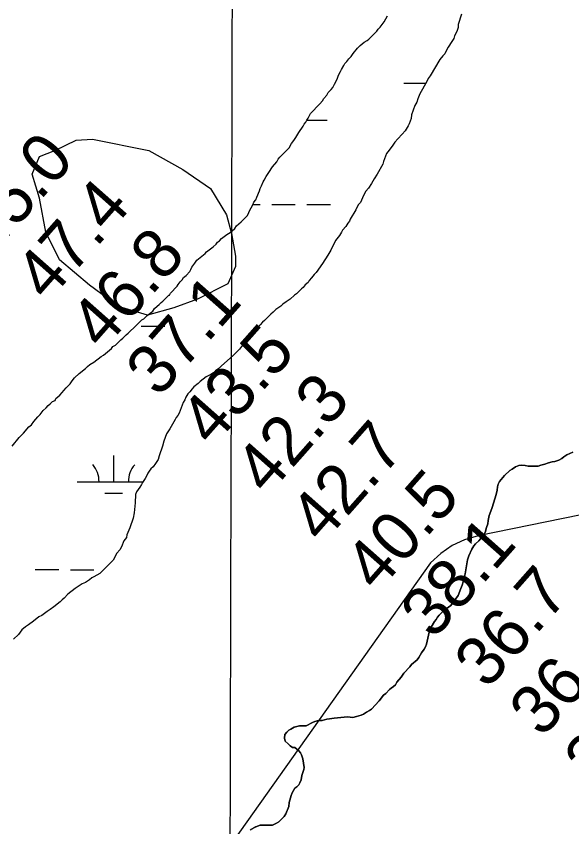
# Model space of a CAD drawing. Extents: x 3172297 to 3210190, y 958463 to 983887.
# Drawn here: x 3191893 to 3192652, y 964695 to 965801 of the extents above; entities that cross this region are included whole.
import ezdxf

# ---------------------------------------------------------------- set-up
doc = ezdxf.new("R2010")
doc.units = 0
for name, color, linetype in [('V-GRID-MAJR', 7, 'Continuous'), ('V-RIVR-RANG', 7, 'Continuous'), ('V-SITE-VEGE', 7, 'Continuous'), ('V-TOPO-MAJR', 7, 'Continuous'), ('V-TOPO-MINR', 7, 'Continuous'), ('V-TOPO-SHOR', 7, 'Continuous'), ('V-WETL-SWMP', 7, 'Continuous')]:
    doc.layers.add(name, color=color, linetype=linetype)

msp = doc.modelspace()

# ---------------------------------------------------------------- linework, layer by layer
at = {"layer": 'V-GRID-MAJR'}
msp.add_spline([(3192183.6, 963880.8), (3192198.6, 969940.7), (3192213.6, 976004.1), (3192228.6, 982067.5), (3192228.6, 982070.9)], degree=3, dxfattribs=at)
at = {"layer": 'V-SITE-VEGE'}
for p, q in [((3192641.5, 965200.1), (3192645.6, 965202.9)), ((3192645.6, 965202.9), (3192649.4, 965204.6)), ((3192649.4, 965204.6), (3192653.8, 965206.4)), ((3192615.3, 965190), (3192620.5, 965191.8)), ((3192620.5, 965191.8), (3192625.3, 965193.2)), ((3192625.3, 965193.2), (3192629.1, 965193.9)), ((3192629.1, 965193.9), (3192634.6, 965195.6)), ((3192634.6, 965195.6), (3192638.7, 965198)), ((3192638.7, 965198), (3192641.5, 965200.1)), ((3192560.3, 965174.4), (3192567.8, 965181.3)), ((3192567.8, 965181.3), (3192570.6, 965183.4)), ((3192570.6, 965183.4), (3192575.4, 965186.5)), ((3192575.4, 965186.5), (3192579.8, 965188.2)), ((3192579.8, 965188.2), (3192582.9, 965188.6)), ((3192582.9, 965188.6), (3192588.8, 965188.2)), ((3192588.8, 965188.2), (3192592.9, 965187.2)), ((3192592.9, 965187.2), (3192606.4, 965187.3)), ((3192606.4, 965187.3), (3192610.1, 965188.7)), ((3192610.1, 965188.7), (3192615.3, 965190)), ((3192553.7, 965166.4), (3192555.8, 965169.2)), ((3192555.8, 965169.2), (3192560.3, 965174.4)), ((3192550.3, 965154.4), (3192550.7, 965159.2)), ((3192550.7, 965159.2), (3192551.7, 965162.6)), ((3192551.7, 965162.6), (3192553.7, 965166.4)), ((3192543.5, 965130.9), (3192549, 965148.8)), ((3192549, 965148.8), (3192550.3, 965154.4)), ((3192539.4, 965119.9), (3192541.5, 965126.1)), ((3192541.5, 965126.1), (3192543.5, 965130.9)), ((3192538.1, 965113), (3192539.4, 965119.9)), ((3192534, 965096.8), (3192535.7, 965103.7)), ((3192535.7, 965103.7), (3192537.4, 965108.5)), ((3192537.4, 965108.5), (3192538.1, 965113)), ((3192525.1, 965085.4), (3192532.3, 965093.7)), ((3192532.3, 965093.7), (3192534, 965096.8)), ((3192518.5, 965078.8), (3192520.6, 965081.2)), ((3192520.6, 965081.2), (3192525.1, 965085.4)), ((3192511.7, 965065), (3192515.5, 965074.3)), ((3192515.5, 965074.3), (3192518.5, 965078.8)), ((3192506.6, 965040.2), (3192510, 965059.5)), ((3192510, 965059.5), (3192511.7, 965065)), ((3192503.9, 965029.5), (3192506.6, 965040.2)), ((3192500.8, 965020.2), (3192502.5, 965025)), ((3192502.5, 965025), (3192503.9, 965029.5)), ((3192497.1, 965010.9), (3192500.8, 965020.2)), ((3192486.8, 964997.4), (3192497.1, 965010.9)), ((3192478.9, 964991.2), (3192486.8, 964997.4)), ((3192466.9, 964978.1), (3192468.6, 964981.2)), ((3192468.6, 964981.2), (3192471, 964983.9)), ((3192471, 964983.9), (3192474.7, 964987.7)), ((3192474.7, 964987.7), (3192478.9, 964991.2)), ((3192460.3, 964967.7), (3192464.8, 964975.3)), ((3192464.8, 964975.3), (3192466.9, 964978.1)), ((3192453.9, 964944.3), (3192457.3, 964960.8)), ((3192457.3, 964960.8), (3192458.6, 964963.6)), ((3192458.6, 964963.6), (3192460.3, 964967.7)), ((3192447, 964932.5), (3192450.8, 964937.4)), ((3192450.8, 964937.4), (3192452.2, 964940.8)), ((3192452.2, 964940.8), (3192453.9, 964944.3)), ((3192440.9, 964922.9), (3192443.3, 964926.3)), ((3192443.3, 964926.3), (3192447, 964932.5)), ((3192430.9, 964913.5), (3192433.3, 964916.7)), ((3192433.3, 964916.7), (3192440.9, 964922.9)), ((3192419.2, 964899.4), (3192423, 964904.9)), ((3192423, 964904.9), (3192430.9, 964913.5)), ((3192411.3, 964889), (3192413.4, 964892.5)), ((3192413.4, 964892.5), (3192419.2, 964899.4)), ((3192398.3, 964877.3), (3192403.4, 964882.5)), ((3192403.4, 964882.5), (3192405.5, 964884.2)), ((3192405.5, 964884.2), (3192408.9, 964886.6)), ((3192408.9, 964886.6), (3192411.3, 964889)), ((3192389, 964867.3), (3192395.2, 964874.9)), ((3192395.2, 964874.9), (3192398.3, 964877.3)), ((3192378.7, 964855.5), (3192389, 964867.3)), ((3192364.3, 964847.5), (3192367.7, 964848.9)), ((3192367.7, 964848.9), (3192371.9, 964851.7)), ((3192371.9, 964851.7), (3192376, 964853.8)), ((3192376, 964853.8), (3192378.7, 964855.5)), ((3192289.2, 964832.8), (3192297.8, 964837.7)), ((3192297.8, 964837.7), (3192301.3, 964839.1)), ((3192301.3, 964839.1), (3192306.1, 964840.1)), ((3192306.1, 964840.1), (3192311.3, 964840.1)), ((3192311.3, 964840.1), (3192317.8, 964841.9)), ((3192317.8, 964841.9), (3192321.3, 964842.6)), ((3192321.3, 964842.6), (3192327.8, 964843.3)), ((3192327.8, 964843.3), (3192332.3, 964844)), ((3192332.3, 964844), (3192346, 964845.1)), ((3192346, 964845.1), (3192353.3, 964844.4)), ((3192353.3, 964844.4), (3192358.1, 964845.5)), ((3192358.1, 964845.5), (3192364.3, 964847.5)), ((3192263.1, 964824.5), (3192265.5, 964826.9)), ((3192265.5, 964826.9), (3192268.3, 964828.6)), ((3192268.3, 964828.6), (3192273.1, 964831.1)), ((3192273.1, 964831.1), (3192280.3, 964832.8)), ((3192280.3, 964832.8), (3192289.2, 964832.8)), ((3192259.7, 964816.2), (3192260, 964821)), ((3192260.7, 964812.1), (3192259.7, 964816.2)), ((3192260, 964821), (3192263.1, 964824.5)), ((3192264.9, 964808.3), (3192260.7, 964812.1)), ((3192267.3, 964805.6), (3192264.9, 964808.3)), ((3192270.7, 964803.2), (3192267.3, 964805.6)), ((3192273.8, 964803.5), (3192270.7, 964803.2)), ((3192279.4, 964799), (3192273.8, 964803.5)), ((3192281.4, 964796.3), (3192279.4, 964799)), ((3192283.2, 964793.2), (3192281.4, 964796.3)), ((3192284.9, 964788), (3192283.2, 964793.2)), ((3192286.7, 964776.3), (3192284.9, 964788)), ((3192283.6, 964765), (3192286.3, 964773.2)), ((3192286.3, 964773.2), (3192286.7, 964776.3)), ((3192280.9, 964755.3), (3192282.6, 964759.4)), ((3192282.6, 964759.4), (3192283.6, 964765)), ((3192274, 964747.7), (3192276.4, 964749.8)), ((3192276.4, 964749.8), (3192279.2, 964752.5)), ((3192279.2, 964752.5), (3192280.9, 964755.3)), ((3192266.2, 964728.4), (3192268.9, 964737.7)), ((3192268.9, 964737.7), (3192270.3, 964741.5)), ((3192270.3, 964741.5), (3192272, 964744.9)), ((3192272, 964744.9), (3192274, 964747.7)), ((3192265.5, 964722.9), (3192266.2, 964728.4)), ((3192261.7, 964712.9), (3192265.5, 964722.9)), ((3192251.8, 964701.8), (3192259.3, 964709.4)), ((3192259.3, 964709.4), (3192261.7, 964712.9)), ((3192220.8, 964695.2), (3192226.7, 964697.3)), ((3192226.7, 964697.3), (3192230.1, 964697.6)), ((3192230.1, 964697.6), (3192234.6, 964697.3)), ((3192234.6, 964697.3), (3192243.2, 964697.3)), ((3192243.2, 964697.3), (3192249, 964700.1)), ((3192249, 964700.1), (3192251.8, 964701.8))]:
    msp.add_line(p, q, dxfattribs=at)
at = {"layer": 'V-TOPO-MAJR'}
msp.add_lwpolyline([(3192687.3, 965125.5), (3192524.2, 965092.4), (3192505.9, 965086.8), (3192488.7, 965079.1), (3192473.4, 965068.3), (3192459.1, 965055.5), (3191992.7, 964398.3), (3191849.4, 964157.8)], dxfattribs=at)
at = {"layer": 'V-TOPO-MINR'}
msp.add_lwpolyline([(3192182.3, 965436), (3192141.1, 965415.5), (3192108.4, 965403.5), (3192072.4, 965393.3), (3192032.9, 965405.4), (3191993.5, 965434.6), (3191952.4, 965469), (3191933.6, 965506.8), (3191925.1, 965553.2), (3191914.8, 965585.8), (3191925.2, 965609.8), (3191945.8, 965618.4), (3191975, 965632.1), (3191997.3, 965633.7), (3192074.5, 965618.2), (3192120.8, 965592.3), (3192158.5, 965566.5), (3192180.7, 965530.4), (3192187.5, 965504.7), (3192192.6, 965473.8), (3192192.6, 965460)], close=True, dxfattribs=at)
at = {"layer": 'V-TOPO-SHOR'}
for points in [[(3192653.8, 965206.4), (3192649.4, 965204.6), (3192645.6, 965202.9), (3192641.5, 965200.1), (3192638.7, 965198), (3192634.6, 965195.6), (3192629.1, 965193.9), (3192625.3, 965193.2), (3192620.5, 965191.8), (3192615.3, 965190), (3192610.1, 965188.7), (3192606.4, 965187.3), (3192592.9, 965187.2), (3192588.8, 965188.2), (3192582.9, 965188.6), (3192579.8, 965188.2), (3192575.4, 965186.5), (3192570.6, 965183.4), (3192567.8, 965181.3), (3192560.3, 965174.4), (3192555.8, 965169.2), (3192553.7, 965166.4), (3192551.7, 965162.6), (3192550.7, 965159.2), (3192550.3, 965154.4), (3192549, 965148.8), (3192543.5, 965130.9)], [(3192543.5, 965130.9), (3192541.5, 965126.1), (3192539.4, 965119.9), (3192538.1, 965113), (3192537.4, 965108.5), (3192535.7, 965103.7), (3192534, 965096.8), (3192532.3, 965093.7), (3192525.1, 965085.4), (3192520.6, 965081.2), (3192518.5, 965078.8), (3192515.5, 965074.3), (3192511.7, 965065), (3192510, 965059.5), (3192506.6, 965040.2), (3192503.9, 965029.5), (3192502.5, 965025), (3192500.8, 965020.2), (3192497.1, 965010.9), (3192486.8, 964997.4), (3192478.9, 964991.2), (3192474.7, 964987.7), (3192471, 964983.9), (3192468.6, 964981.2), (3192466.9, 964978.1), (3192464.8, 964975.3), (3192460.3, 964967.7), (3192458.6, 964963.6), (3192457.3, 964960.8), (3192453.9, 964944.3), (3192452.2, 964940.8), (3192450.8, 964937.4), (3192447, 964932.5), (3192443.3, 964926.3), (3192440.9, 964922.9), (3192433.3, 964916.7), (3192430.9, 964913.5), (3192423, 964904.9), (3192419.2, 964899.4), (3192413.4, 964892.5), (3192411.3, 964889), (3192408.9, 964886.6), (3192405.5, 964884.2), (3192403.4, 964882.5), (3192398.3, 964877.3), (3192395.2, 964874.9), (3192389, 964867.3), (3192378.7, 964855.5), (3192376, 964853.8), (3192371.9, 964851.7), (3192367.7, 964848.9), (3192364.3, 964847.5), (3192358.1, 964845.5), (3192353.3, 964844.4), (3192346, 964845.1), (3192332.3, 964844), (3192327.8, 964843.3), (3192321.3, 964842.6), (3192317.8, 964841.9), (3192311.3, 964840.1), (3192306.1, 964840.1), (3192301.3, 964839.1), (3192297.8, 964837.7), (3192289.2, 964832.8), (3192280.3, 964832.8), (3192273.1, 964831.1), (3192268.3, 964828.6), (3192265.5, 964826.9), (3192263.1, 964824.5), (3192260, 964821), (3192259.7, 964816.2), (3192260.7, 964812.1), (3192264.9, 964808.3), (3192267.3, 964805.6), (3192270.7, 964803.2), (3192273.8, 964803.5), (3192279.4, 964799), (3192281.4, 964796.3), (3192283.2, 964793.2), (3192284.9, 964788), (3192286.7, 964776.3), (3192286.3, 964773.2), (3192283.6, 964765), (3192282.6, 964759.4), (3192280.9, 964755.3), (3192279.2, 964752.5), (3192276.4, 964749.8), (3192274, 964747.7), (3192272, 964744.9), (3192270.3, 964741.5), (3192268.9, 964737.7), (3192266.2, 964728.4), (3192265.5, 964722.9), (3192261.7, 964712.9), (3192259.3, 964709.4), (3192251.8, 964701.8), (3192249, 964700.1), (3192243.2, 964697.3), (3192234.6, 964697.3), (3192230.1, 964697.6), (3192226.7, 964697.3)], [(3192226.7, 964697.3), (3192220.8, 964695.2), (3192212.9, 964690.7)]]:
    msp.add_lwpolyline(points, dxfattribs=at)
at = {"layer": 'V-WETL-SWMP'}
for p, q in [((3192422.8, 965710.3), (3192452.8, 965710.2)), ((3192290.3, 965659.8), (3192318.1, 965659.8)), ((3192216.6, 965544.6), (3192226.4, 965544.6)), ((3192242.4, 965544.5), (3192274.4, 965544.4)), ((3192290.4, 965544.4), (3192322.4, 965544.3)), ((3192064.1, 965378.5), (3192096.1, 965378.4)), ((3192026.4, 965166), (3192026.5, 965202)), ((3191976.4, 965166.1), (3192066.3, 965165.9)), ((3192014.4, 965150.6), (3192038.4, 965150.5)), ((3191919.3, 965046.1), (3191951.3, 965046.1)), ((3191967.3, 965046), (3191999.3, 965046))]:
    msp.add_line(p, q, dxfattribs=at)
for points in [[(3192501.5, 965804.1), (3192496.9, 965790), (3192496.9, 965786), (3192495.6, 965781.9), (3192494.2, 965778.6), (3192492.2, 965774.5), (3192490.9, 965771.1), (3192488.2, 965767.1), (3192483.5, 965759), (3192480.8, 965754.3), (3192478.8, 965750.3), (3192476.2, 965747.6), (3192472.1, 965742.2), (3192458.8, 965719.9), (3192456.1, 965716.5), (3192454.1, 965712.5), (3192444.7, 965695.6), (3192442, 965688.9), (3192440.7, 965684.2), (3192438, 965679.5), (3192433.4, 965666.7), (3192432.7, 965662), (3192430, 965654.6), (3192428.7, 965651.9), (3192424.7, 965645.1), (3192420.7, 965640.4), (3192414.6, 965634.3), (3192410.6, 965629.6), (3192407.9, 965625.6), (3192402.6, 965618.8), (3192399.2, 965614.1), (3192395.2, 965603.3), (3192393.9, 965599.3), (3192386.5, 965585.8), (3192382.5, 965579.7), (3192378.5, 965573), (3192374.5, 965566.9), (3192371.1, 965562.9), (3192367.8, 965556.8), (3192363.8, 965547.4), (3192360.4, 965544), (3192357.1, 965537.2), (3192349.7, 965524.4), (3192348.4, 965521.7), (3192346.4, 965519), (3192343.7, 965514.3), (3192339, 965509.6), (3192337.7, 965506.9), (3192335, 965502.2), (3192329.6, 965495.4), (3192322.9, 965482), (3192318.9, 965475.2), (3192311.6, 965463.8), (3192302.9, 965451.6), (3192300.2, 965448.9), (3192296.8, 965444.2), (3192293.5, 965440.8), (3192292.1, 965438.1), (3192288.1, 965434.8), (3192285.4, 965431.4), (3192282.8, 965429.4), (3192276, 965422.6), (3192273.4, 965420.6), (3192267.3, 965415.2), (3192262, 965411.8), (3192257.3, 965408.4), (3192254.6, 965405.7), (3192251.9, 965403.7), (3192247.9, 965401), (3192244.5, 965397.6), (3192241.1, 965394.9), (3192232.4, 965386.1), (3192229.7, 965384.1), (3192226.4, 965380.1), (3192223.7, 965377.4), (3192219.7, 965372.6), (3192211.6, 965364.5), (3192208.3, 965359.8), (3192203.6, 965354.4), (3192198.2, 965347), (3192190.2, 965338.9), (3192173.4, 965324), (3192170.1, 965320.7), (3192165.4, 965317.3), (3192162.7, 965314.6), (3192159.3, 965312.6), (3192152.6, 965309.2), (3192144.6, 965303.1), (3192141.9, 965300.4), (3192135.8, 965295.7), (3192133.8, 965293), (3192130.5, 965288.9)], [(3192140, 965468.6), (3192144.7, 965472), (3192151.4, 965477.4), (3192153.4, 965480.1), (3192162.1, 965486.8), (3192166.2, 965490.2), (3192168.2, 965492.9), (3192170.9, 965494.9), (3192173.5, 965498.3), (3192180.9, 965503.7), (3192185.6, 965506.4), (3192188.3, 965508.4), (3192191.7, 965511.8), (3192194.3, 965515.2), (3192200.4, 965520.6), (3192209.1, 965529.4), (3192211.1, 965533.4), (3192212.4, 965536.8), (3192214.4, 965540.1), (3192216.4, 965544.2), (3192217.8, 965547.6), (3192220.5, 965550.9), (3192221.8, 965554.3), (3192225.8, 965563.1), (3192226.5, 965566.4), (3192228.5, 965569.8), (3192230.5, 965575.2), (3192231.8, 965577.9), (3192234.5, 965582.6), (3192238.5, 965588), (3192243.2, 965596.1), (3192249.2, 965602.8), (3192251.2, 965606.2), (3192253.2, 965608.9), (3192266, 965621.7), (3192269.3, 965627.8), (3192272.7, 965631.8), (3192275.4, 965635.9), (3192279.4, 965642.6), (3192285.4, 965651.4), (3192286.7, 965654.1), (3192288.7, 965656.8), (3192290.1, 965659.5), (3192292.1, 965662.2), (3192295.4, 965668.9), (3192308.2, 965681.7), (3192311.5, 965685.8), (3192313.5, 965689.2), (3192317.6, 965693.9), (3192319.6, 965697.3), (3192323.6, 965701.3), (3192325.6, 965704), (3192328.3, 965708.7), (3192331.6, 965715.5), (3192332.9, 965719.5), (3192334.3, 965722.9), (3192336.3, 965726.2), (3192337.6, 965728.9), (3192341, 965734.3), (3192342.3, 965737), (3192345, 965739.7), (3192347.7, 965743.1), (3192351, 965746.5), (3192353.7, 965750.5), (3192359.7, 965757.9), (3192363.1, 965761.3), (3192368.4, 965766), (3192372.5, 965768.1), (3192375.2, 965770.1), (3192385.9, 965780.9), (3192387.9, 965783.6), (3192390.6, 965786.3), (3192395.9, 965793.7), (3192400.6, 965801.8)], [(3191887.8, 965214.8), (3191897.2, 965226.3), (3191903.3, 965232.3), (3191910.6, 965241.1), (3191914, 965243.8), (3191917.3, 965248.5), (3191922.7, 965254.6), (3191926, 965258), (3191930.1, 965263.4), (3191934.1, 965266.8), (3191936.8, 965270.1), (3191939.5, 965272.2), (3191942.8, 965275.5), (3191946.2, 965276.9), (3191947.5, 965279.6), (3191952.9, 965284.3), (3191956.2, 965287.7), (3191958.2, 965290.4), (3191961.6, 965294.4), (3191967, 965299.8), (3191969.6, 965303.9), (3191973, 965307.9), (3191979, 965314), (3191987.7, 965320.8), (3191990.4, 965323.5), (3191993.8, 965326.2), (3191999.2, 965329.5), (3192009.2, 965337), (3192012.6, 965339), (3192023.3, 965347.8), (3192025.3, 965350.5), (3192028.7, 965352.5), (3192036.1, 965359.9), (3192038.7, 965362), (3192043.4, 965366.7), (3192046.1, 965368.7), (3192056.9, 965379.5), (3192064.9, 965386.9), (3192067.6, 965388.3), (3192072.3, 965393), (3192079.7, 965399.1), (3192082.3, 965402.5), (3192085.7, 965405.8), (3192088.4, 965407.9), (3192091.1, 965410.6), (3192093.7, 965412.6), (3192101.8, 965420.7), (3192102.5, 965420.7), (3192103.8, 965423.4), (3192113.2, 965432.8), (3192114.5, 965435.5), (3192117.2, 965438.9), (3192119.9, 965441.6), (3192121.9, 965445), (3192125.3, 965447.7), (3192130.6, 965453.1), (3192132, 965455.8), (3192133.3, 965459.1), (3192137.3, 965464.5), (3192140, 965468.6)], [(3192130.5, 965288.9), (3192127.8, 965286.2), (3192125.1, 965281.5), (3192123.8, 965278.1), (3192121.1, 965274.1), (3192115.8, 965259.9), (3192113.8, 965256.6), (3192111.8, 965253.9), (3192110.4, 965251.2), (3192103.1, 965238.4), (3192098.4, 965231.6), (3192095, 965221.5), (3192093, 965214.8), (3192088.4, 965201.3), (3192087, 965196.6), (3192083.7, 965191.2), (3192080.4, 965186.5), (3192077, 965183.8), (3192075, 965180.4), (3192073, 965177.7), (3192071, 965173.7), (3192069.6, 965170.3), (3192065.6, 965164.9), (3192064.3, 965162.2), (3192062.3, 965158.8), (3192057.6, 965152.1), (3192056.3, 965148.7), (3192055.6, 965137.3), (3192054.3, 965123.8), (3192053, 965116.4), (3192048.3, 965103), (3192044.3, 965093.5), (3192043.7, 965090.2), (3192040.3, 965085.4), (3192037, 965077.4), (3192035, 965073.3), (3192030.9, 965068.6), (3192025.6, 965059.2), (3192007.5, 965040.9), (3191999.4, 965036.2), (3191996.7, 965034.8), (3191993.4, 965032.1), (3191988, 965028.8), (3191983.3, 965026.7), (3191973.9, 965020.6), (3191963.9, 965012.5), (3191958.5, 965007.1), (3191955.8, 965005.1), (3191953.1, 965002.4), (3191944.4, 964995.6), (3191939.7, 964991.6), (3191935.7, 964988.9), (3191928.3, 964983.5), (3191924.3, 964981.5), (3191916.9, 964976), (3191910.2, 964970.6), (3191906.1, 964967.9), (3191900.8, 964963.9), (3191896.1, 964957.8), (3191889.4, 964951.1)]]:
    msp.add_lwpolyline(points, dxfattribs=at)
for centre, start, end in [((3191971.2, 965166.6), 359.0865, 40.6302), ((3192081.7, 965166.3), 139.0865, 180.6302)]:
    msp.add_arc(centre, 35.2, start, end, dxfattribs=at)

# ---------------------------------------------------------------- texts
at = {"layer": 'V-RIVR-RANG'}
for s, p in [('45.0', (3191859.3, 965473.9)), ('47.4', (3191936.2, 965410)), ('46.8', (3192011.3, 965343.9)), ('37.1', (3192087.9, 965279.6)), ('43.5', (3192161.4, 965211.8)), ('42.3', (3192236.5, 965145.7)), ('42.7', (3192311.5, 965079.6)), ('40.5', (3192386.6, 965013.6)), ('38.1', (3192463.2, 964949.3)), ('36.7', (3192536.7, 964881.4)), ('36.4', (3192611.8, 964815.3)), ('37.8', (3192686.8, 964749.2))]:
    msp.add_text(s, height=67, rotation=48.4983, dxfattribs=at).set_placement(p)

doc.saveas('drawing.dxf')
